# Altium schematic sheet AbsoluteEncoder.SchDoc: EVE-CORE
size A4; Organization: Ingenia Motion Control; Address1: Carrer Avila, 124, 2B; Address2: 08018 Barcelona Spain; Address3: www.ingeniamc.com; Address4: www.ingeniamc.com; Documentation: https://doc.ingeniamc.com/x/coAZBg
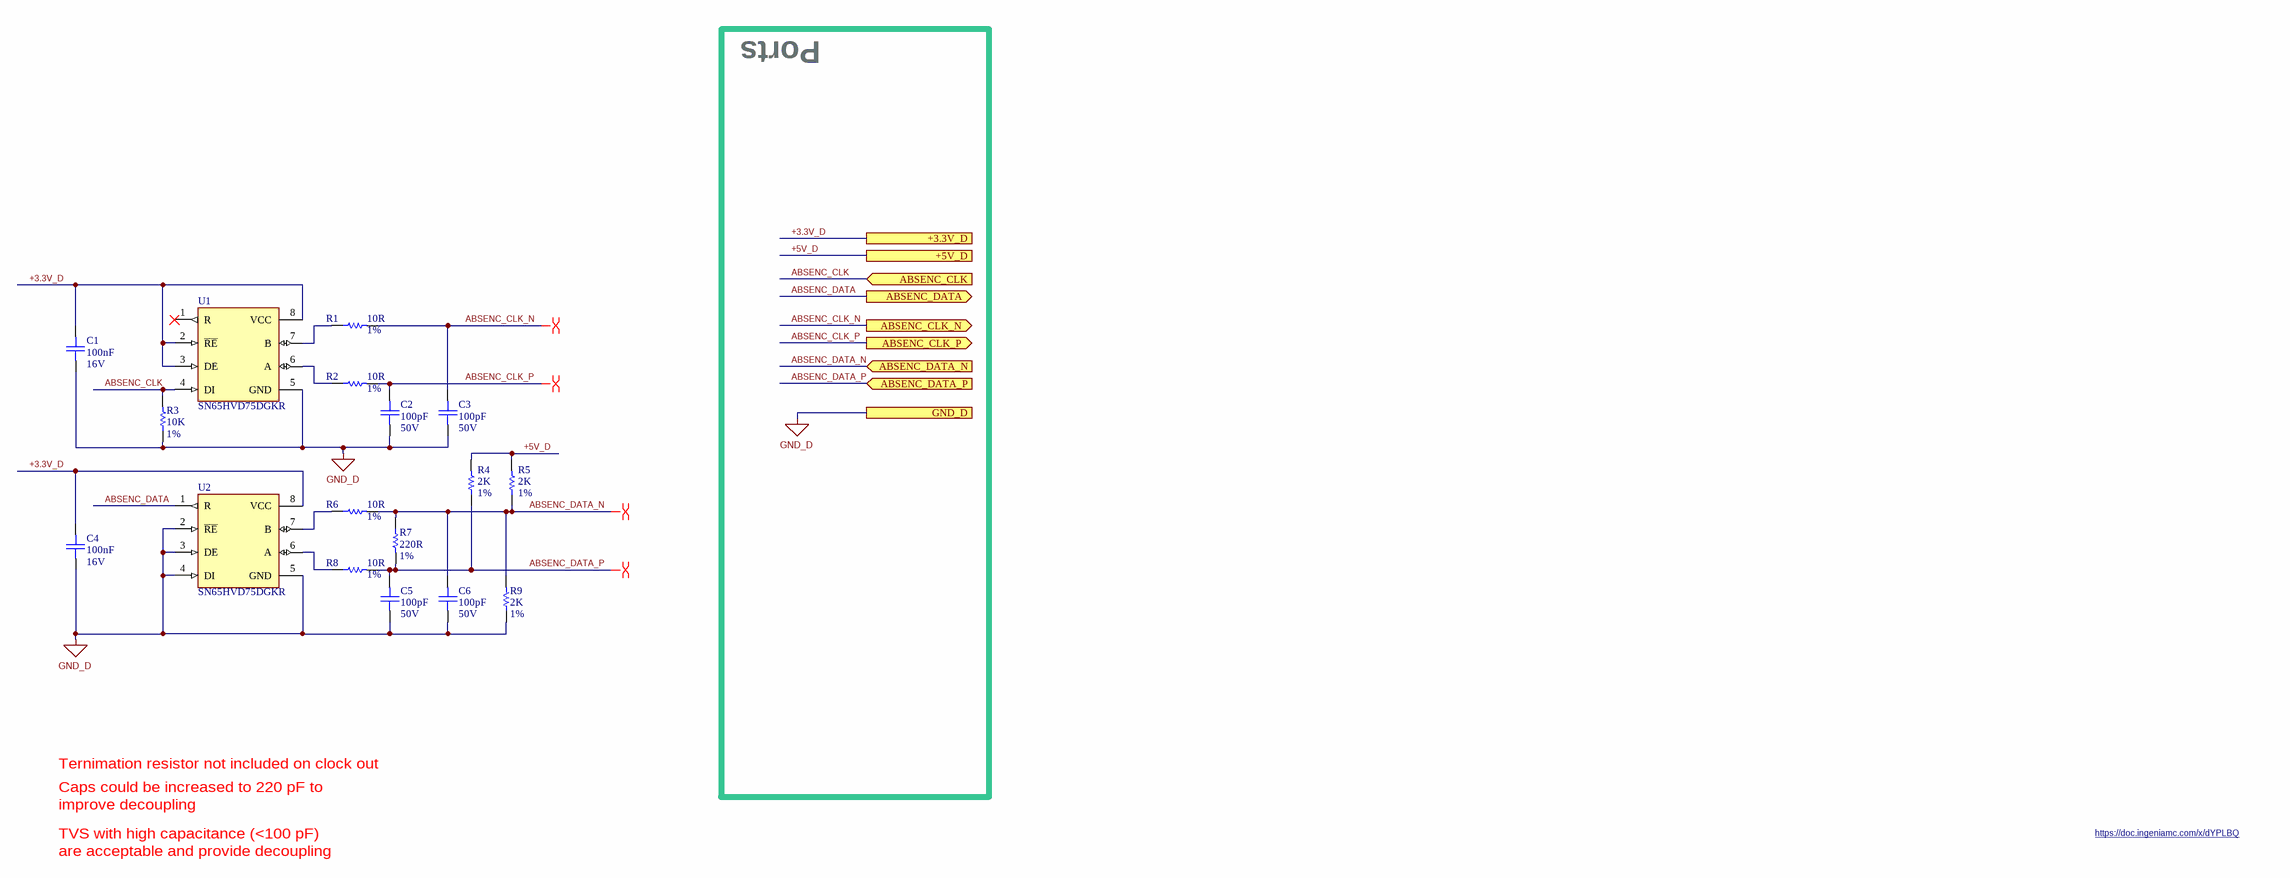
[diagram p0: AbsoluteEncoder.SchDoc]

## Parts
C1  value 100nF  Voltage: 16V  [C_0402]  (hidden comment: C_0402--100nF--16V)
C2  value 100pF  Voltage: 50V  [C_0402]  (hidden comment: C_0402--100pF--50V)
C3  value 100pF  Voltage: 50V  [C_0402]  (hidden comment: C_0402--100pF--50V)
C4  value 100nF  Voltage: 16V  [C_0402]  (hidden comment: C_0402--100nF--16V)
C5  value 100pF  Voltage: 50V  [C_0402]  (hidden comment: C_0402--100pF--50V)
C6  value 100pF  Voltage: 50V  [C_0402]  (hidden comment: C_0402--100pF--50V)
R1  value 10R  Tolerance: 1%  [R_0603]  (hidden comment: R_0603--10R--1%)
R2  value 10R  Tolerance: 1%  [R_0603]  (hidden comment: R_0603--10R--1%)
R3  value 10K  Tolerance: 1%  [R_0402]  (hidden comment: R_0402--10K--1%)
R4  value 2K  Tolerance: 1%  [R_0402]  (hidden comment: R_0402--2K--1%)
R5  value 2K  Tolerance: 1%  [R_0402]  (hidden comment: R_0402--2K--1%)
R6  value 10R  Tolerance: 1%  [R_0603]  (hidden comment: R_0603--10R--1%)
R7  value 220R  Tolerance: 1%  [R_0603]  (hidden comment: R_0603--220R--1%)
R8  value 10R  Tolerance: 1%  [R_0603]  (hidden comment: R_0603--10R--1%)
R9  value 2K  Tolerance: 1%  [R_0402]  (hidden comment: R_0402--2K--1%)
U1  SN65HVD75DGKR  [MSOP8_3x3_065P]
U2  SN65HVD75DGKR  [MSOP8_3x3_065P]

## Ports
+3.3V_D, +5V_D, ABSENC_CLK (in), ABSENC_CLK_N (out), ABSENC_CLK_P (out), ABSENC_DATA (out), ABSENC_DATA_N (in), ABSENC_DATA_P (in), GND_D

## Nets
GND_D: C1.2 C2.2 C3.2 C4.2 C5.2 C6.2 R3.1 R9.1 U1.5(GND) U2.2(~{RE}) U2.3(DE) U2.4(DI) U2.5(GND) ; port GND_D
+3.3V_D: C1.1 C4.1 U1.2(~{RE}) U1.3(DE) U1.8(VCC) U2.8(VCC) ; port +3.3V_D
+5V_D: R4.2 R5.2 ; port +5V_D
ABSENC_CLK: R3.2 U1.4(DI) ; port ABSENC_CLK
ABSENC_CLK_N: C3.1 R1.2 ; port ABSENC_CLK_N
ABSENC_CLK_P: C2.1 R2.2 ; port ABSENC_CLK_P
ABSENC_DATA: U2.1(R) ; port ABSENC_DATA
ABSENC_DATA_N: C6.1 R5.1 R6.2 R7.1 R9.2 ; port ABSENC_DATA_N
ABSENC_DATA_P: C5.1 R4.1 R7.2 R8.2 ; port ABSENC_DATA_P
NetR1_1: R1.1 U1.7(B)
NetR2_1: R2.1 U1.6(A)
NetR6_1: R6.1 U2.7(B)
NetR8_1: R8.1 U2.6(A)

Not connected (* = marked no-connect by the designer): U1 1(R)*

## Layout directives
differential pair: ABSENC_CLK_N, ABSENC_CLK_P, ABSENC_DATA_N, ABSENC_DATA_P

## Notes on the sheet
- Ports
- Ternimation resistor not included on clock out
- Caps could be increased to 220 pF to
- TVS with high capacitance (<100 pF)
- improve decoupling
- https://doc.ingeniamc.com/x/dYPLBQ
- are acceptable and provide decoupling

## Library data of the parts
C1 C4 = C_0402[[/\]]100nF[[/\]]16V: CAP CER 100nF 16V X7R 0402; ManufacturerName: Murata; ManufacturerPN: GRM155R71C104KA88D; AlternativeManufacturer: Wurth; IsPreferred: 1; IngeniaID: 672; InternalStock: 0; AlternativePN: 885012205037; MTBF55h: 36129613; TemperatureMaxC: 125; TemperatureMinC: -55
C2 C3 C5 C6 = C_0402[[/\]]100pF[[/\]]50V: CAP CER 100pF 50V NP0/C0G 0402; ManufacturerName: Yageo; ManufacturerPN: CC0402JRNPO9BN101; AlternativeManufacturer: Kemet; IsPreferred: 0; IngeniaID: 1451; AdditionalInformation: NP0; AlternativePN: C0402H101J5GAFT1K0; MTBF55h: 77243743; TemperatureMaxC: 125; TemperatureMinC: -55
R1 R2 R6 R8 = R_0603[[/\]]10R[[/\]]1%: Resistor, 0603, 10ohm, 1%; ManufacturerName: Multicomp; ManufacturerPN: MC 0.063W 0603 1% 10R; AlternativeManufacturer: Yageo; IsPreferred: 0; IsGeneric: 1; IngeniaID: 781; AlternativePN: RC0603FR-0710RL; TemperatureMaxC: 155; TemperatureMinC: -55
R3 = R_0402[[/\]]10K[[/\]]1%: RESISTOR 10K OHM 1/16W 1% 0402 SMD; ManufacturerName: Stackpole Electronics; ManufacturerPN: RMCF0402FT10K0; AlternativeManufacturer: Vishay Dale; IsPreferred: 0; IngeniaID: 685; IsGeneric: 1; AlternativePN: CRCW040210K0FKED; MTBF55h: 91649788; TemperatureMaxC: 155; TemperatureMinC: -55
R4 R5 R9 = R_0402[[/\]]2K[[/\]]1%: RES 2K OHM 1/16W 1% 0402 SMD; ManufacturerName: Stackpole Electronics; ManufacturerPN: RMCF0402FT2K00; AlternativeManufacturer: Panasonic Electronic Components; IsPreferred: 0; IsGeneric: 1; IngeniaID: 689; AlternativePN: ERJ-2RKF2001X; MTBF55h: 91649788; TemperatureMaxC: 155; TemperatureMinC: -55
R7 = R_0603[[/\]]220R[[/\]]1%: Resistor 1%; ManufacturerName: Panasonic; ManufacturerPN: ERJ3EKF2200V; AlternativeManufacturer: Yageo; IsPreferred: 0; IsGeneric: 1; IngeniaID: 822; TemperatureMaxC: 155; TemperatureMinC: -55; AlternativePN: RC0603FR-07220RL
U1 U2 = SN65HVD75DGKR: RS-422/485 Transceiver (1 TX/ 1 RX), 20Mbps 3.3V; ManufacturerName: Texas Instruments; IsPreferred: 0; IngeniaID: 3105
